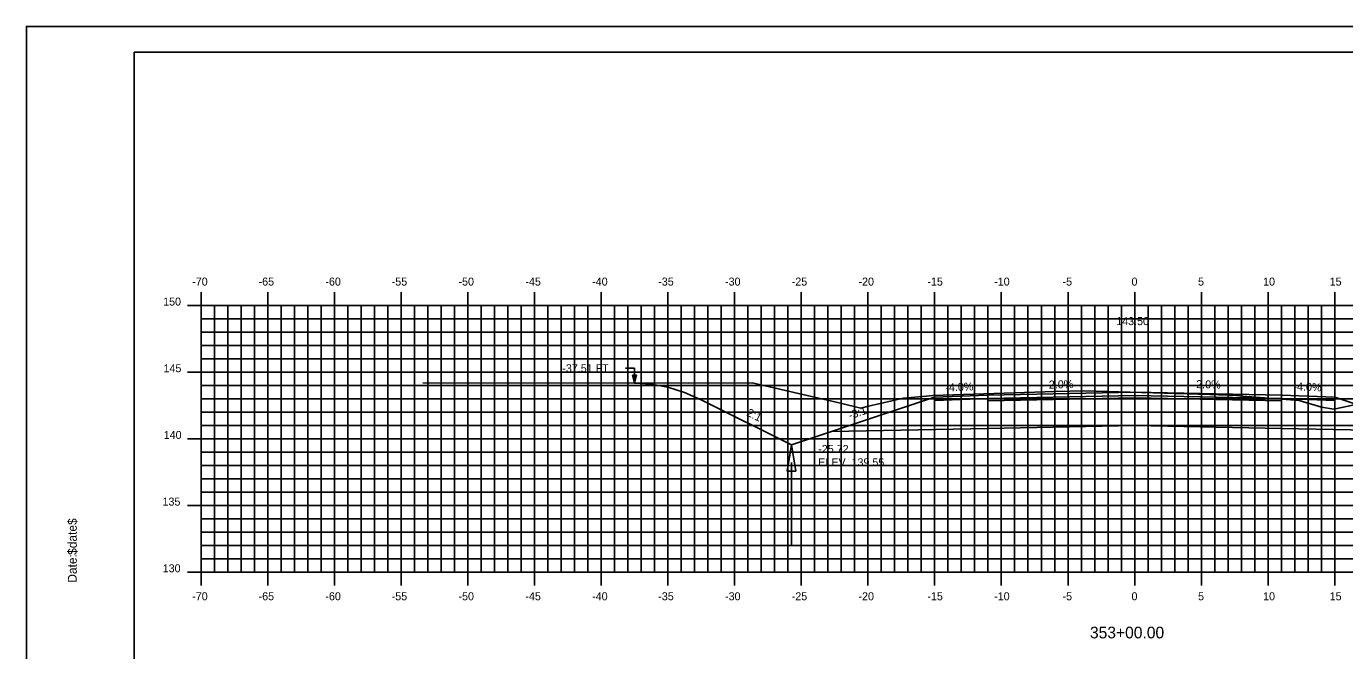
# Model space of a CAD drawing. Extents: x 1144972 to 1145142, y 608981 to 609091.
# Drawn here: x 1144972.3 to 1145071.1, y 609044.5 to 609091.3 of the extents above; entities that cross this region are included whole.
import ezdxf

# ---------------------------------------------------------------- set-up
doc = ezdxf.new("R2010")
doc.units = 0
for name, color, linetype in [('ANNOTATION', 7, 'Continuous'), ('BORDER', 7, 'Continuous'), ('D_Drainage_Ditch_Line', 7, 'Continuous'), ('D_Roadway_Centerline', 7, 'Continuous'), ('D_Roadway_Centerline_Text', 7, 'Continuous'), ('D_Roadway_Edge_Shoulder', 7, 'Continuous'), ('D_Roadway_Edge_TW', 7, 'Continuous'), ('D_Roadway_Pavement', 7, 'Continuous'), ('D_Roadway_SlopeLines', 7, 'Continuous'), ('D_Roadway_SubGrade', 7, 'Continuous'), ('D_Text_Standard', 7, 'Continuous'), ('H_V ANNOTATION', 7, 'Continuous'), ('MAJOR', 7, 'Continuous'), ('MINOR', 7, 'Continuous'), ('PLOT BOUNDARY', 7, 'Continuous'), ('S_Roadway_Centerline', 7, 'Continuous')]:
    doc.layers.add(name, color=color, linetype=linetype)

msp = doc.modelspace()

# ---------------------------------------------------------------- linework, layer by layer
msp.add_lwpolyline([(1145017.869, 609064.526), (1145019.119, 609064.447), (1145020.369, 609064.213), (1145021.619, 609063.822), (1145022.869, 609063.275), (1145029.651, 609059.884), (1145032.651, 609060.884), (1145040.374, 609063.458), (1145040.375, 609063.458), (1145044.375, 609063.618), (1145055.375, 609063.838), (1145066.375, 609063.618), (1145070.375, 609063.458), (1145078.099, 609060.884), (1145081.099, 609059.884), (1145086.647, 609062.658), (1145087.897, 609063.206), (1145089.147, 609063.599), (1145090.397, 609063.839), (1145091.647, 609063.924)])
at = {"layer": 'BORDER'}
msp.add_lwpolyline([(1144980.376, 608984.335), (1145140.376, 608984.335), (1145140.376, 609089.335), (1144980.376, 609089.335)], close=True, dxfattribs=at)
at = {"layer": 'D_Drainage_Ditch_Line'}
msp.add_line((1145029.651, 609058.571), (1145029.65, 609052.328), dxfattribs=at)
msp.add_lwpolyline([(1145029.979, 609057.915), (1145029.323, 609057.915), (1145029.651, 609059.884)], close=True, dxfattribs=at)
at = {"layer": 'D_Roadway_Edge_Shoulder'}
for points in [[(1145044.375, 609063.618), (1145040.375, 609063.458), (1145040.375, 609063.208), (1145044.375, 609063.368)], [(1145066.375, 609063.618), (1145070.375, 609063.458), (1145070.375, 609063.208), (1145066.375, 609063.368)]]:
    msp.add_lwpolyline(points, close=True, dxfattribs=at)
at = {"layer": 'D_Roadway_Edge_TW'}
msp.add_lwpolyline([(1145044.375, 609063.368), (1145044.375, 609063.618), (1145055.375, 609063.838), (1145066.375, 609063.618), (1145066.375, 609063.368), (1145055.375, 609063.588)], close=True, dxfattribs=at)
at = {"layer": 'D_Roadway_Pavement'}
msp.add_lwpolyline([(1145044.375, 609063.202), (1145044.375, 609063.368), (1145055.375, 609063.588), (1145066.375, 609063.368), (1145066.375, 609063.202), (1145055.375, 609063.422)], close=True, dxfattribs=at)
at = {"layer": 'D_Roadway_SlopeLines'}
for points in [[(1145029.651, 609059.884), (1145022.869, 609063.275), (1145021.619, 609063.822), (1145020.369, 609064.213), (1145019.119, 609064.447), (1145017.869, 609064.526)], [(1145032.651, 609060.884), (1145029.651, 609059.884)]]:
    msp.add_lwpolyline(points, dxfattribs=at)
at = {"layer": 'D_Roadway_SubGrade'}
for points in [[(1145044.375, 609063.202), (1145044.375, 609063.368), (1145040.375, 609063.208), (1145040.375, 609063.458), (1145040.374, 609063.458), (1145032.651, 609060.884), (1145044.375, 609061.118)], [(1145044.375, 609061.118), (1145044.375, 609063.202), (1145055.375, 609063.422), (1145066.375, 609063.202), (1145066.375, 609061.118), (1145055.375, 609061.338)], [(1145066.375, 609063.202), (1145066.375, 609063.368), (1145070.375, 609063.208), (1145070.375, 609063.458), (1145070.376, 609063.458), (1145078.099, 609060.884), (1145066.375, 609061.118)]]:
    msp.add_lwpolyline(points, close=True, dxfattribs=at)
at = {"layer": 'D_Text_Standard'}
msp.add_lwpolyline([(1145017.869, 609064.525), (1145017.871, 609065.634), (1145017.191, 609065.634)], dxfattribs=at)
msp.add_lwpolyline([(1145017.869, 609064.525), (1145017.725, 609065.107), (1145018.016, 609065.107)], close=True, dxfattribs=at)
at = {"layer": 'MAJOR'}
for p, q in [((1144985.375, 609071.337), (1144985.375, 609070.335)), ((1144990.375, 609071.337), (1144990.375, 609070.335)), ((1144995.375, 609071.337), (1144995.375, 609070.335)), ((1145000.375, 609071.337), (1145000.375, 609070.335)), ((1145005.375, 609071.337), (1145005.375, 609070.335)), ((1145010.375, 609071.337), (1145010.375, 609070.335)), ((1145015.375, 609071.337), (1145015.375, 609070.335)), ((1145020.375, 609071.337), (1145020.375, 609070.335)), ((1145025.375, 609071.337), (1145025.375, 609070.335)), ((1145030.375, 609071.337), (1145030.375, 609070.335)), ((1145035.375, 609071.337), (1145035.375, 609070.335)), ((1145040.375, 609071.337), (1145040.375, 609070.335)), ((1145045.375, 609071.337), (1145045.375, 609070.335)), ((1145050.375, 609071.337), (1145050.375, 609070.335)), ((1145055.375, 609071.337), (1145055.375, 609070.335)), ((1145060.375, 609071.337), (1145060.375, 609070.335)), ((1145065.375, 609071.337), (1145065.375, 609070.335)), ((1145070.375, 609071.337), (1145070.375, 609070.335)), ((1144984.373, 609070.335), (1144985.375, 609070.335)), ((1144985.375, 609070.335), (1145125.375, 609070.335)), ((1144985.375, 609050.335), (1144985.375, 609070.335)), ((1144985.375, 609050.335), (1144985.375, 609070.335)), ((1144985.375, 609070.335), (1145125.375, 609070.335)), ((1144990.375, 609050.335), (1144990.375, 609070.335)), ((1144995.375, 609050.335), (1144995.375, 609070.335)), ((1145000.375, 609050.335), (1145000.375, 609070.335)), ((1145005.375, 609050.335), (1145005.375, 609070.335)), ((1145010.375, 609050.335), (1145010.375, 609070.335)), ((1145015.375, 609050.335), (1145015.375, 609070.335)), ((1145020.375, 609050.335), (1145020.375, 609070.335)), ((1145025.375, 609050.335), (1145025.375, 609070.335)), ((1145030.375, 609050.335), (1145030.375, 609070.335)), ((1145035.375, 609050.335), (1145035.375, 609070.335)), ((1145040.375, 609050.335), (1145040.375, 609070.335)), ((1145045.375, 609050.335), (1145045.375, 609070.335)), ((1145050.375, 609050.335), (1145050.375, 609070.335)), ((1145055.375, 609050.335), (1145055.375, 609070.335)), ((1145060.375, 609050.335), (1145060.375, 609070.335)), ((1145065.375, 609050.335), (1145065.375, 609070.335)), ((1145070.375, 609050.335), (1145070.375, 609070.335)), ((1144984.373, 609065.335), (1144985.375, 609065.335)), ((1144985.375, 609065.335), (1145125.375, 609065.335)), ((1144984.373, 609060.335), (1144985.375, 609060.335)), ((1144985.375, 609060.335), (1145125.375, 609060.335)), ((1144984.373, 609055.335), (1144985.375, 609055.335)), ((1144985.375, 609055.335), (1145125.375, 609055.335)), ((1144984.373, 609050.335), (1144985.375, 609050.335)), ((1144985.375, 609050.335), (1145125.375, 609050.335)), ((1144985.375, 609050.335), (1145125.375, 609050.335)), ((1144985.375, 609049.333), (1144985.375, 609050.335)), ((1144990.375, 609049.333), (1144990.375, 609050.335)), ((1144995.375, 609049.333), (1144995.375, 609050.335)), ((1145000.375, 609049.333), (1145000.375, 609050.335)), ((1145005.375, 609049.333), (1145005.375, 609050.335)), ((1145010.375, 609049.333), (1145010.375, 609050.335)), ((1145015.375, 609049.333), (1145015.375, 609050.335)), ((1145020.375, 609049.333), (1145020.375, 609050.335)), ((1145025.375, 609049.333), (1145025.375, 609050.335)), ((1145030.375, 609049.333), (1145030.375, 609050.335)), ((1145035.375, 609049.333), (1145035.375, 609050.335)), ((1145040.375, 609049.333), (1145040.375, 609050.335)), ((1145045.375, 609049.333), (1145045.375, 609050.335)), ((1145050.375, 609049.333), (1145050.375, 609050.335)), ((1145055.375, 609049.333), (1145055.375, 609050.335)), ((1145060.375, 609049.333), (1145060.375, 609050.335)), ((1145065.375, 609049.333), (1145065.375, 609050.335)), ((1145070.375, 609049.333), (1145070.375, 609050.335))]:
    msp.add_line(p, q, dxfattribs=at)
at = {"layer": 'MINOR'}
for p, q in [((1144986.375, 609050.335), (1144986.375, 609070.335)), ((1144987.375, 609050.335), (1144987.375, 609070.335)), ((1144988.375, 609050.335), (1144988.375, 609070.335)), ((1144989.375, 609050.335), (1144989.375, 609070.335)), ((1144991.375, 609050.335), (1144991.375, 609070.335)), ((1144992.375, 609050.335), (1144992.375, 609070.335)), ((1144993.375, 609050.335), (1144993.375, 609070.335)), ((1144994.375, 609050.335), (1144994.375, 609070.335)), ((1144996.375, 609050.335), (1144996.375, 609070.335)), ((1144997.375, 609050.335), (1144997.375, 609070.335)), ((1144998.375, 609050.335), (1144998.375, 609070.335)), ((1144999.375, 609050.335), (1144999.375, 609070.335)), ((1145001.375, 609050.335), (1145001.375, 609070.335)), ((1145002.375, 609050.335), (1145002.375, 609070.335)), ((1145003.375, 609050.335), (1145003.375, 609070.335)), ((1145004.375, 609050.335), (1145004.375, 609070.335)), ((1145006.375, 609050.335), (1145006.375, 609070.335)), ((1145007.375, 609050.335), (1145007.375, 609070.335)), ((1145008.375, 609050.335), (1145008.375, 609070.335)), ((1145009.375, 609050.335), (1145009.375, 609070.335)), ((1145011.375, 609050.335), (1145011.375, 609070.335)), ((1145012.375, 609050.335), (1145012.375, 609070.335)), ((1145013.375, 609050.335), (1145013.375, 609070.335)), ((1145014.375, 609050.335), (1145014.375, 609070.335)), ((1145016.375, 609050.335), (1145016.375, 609070.335)), ((1145017.375, 609050.335), (1145017.375, 609070.335)), ((1145018.375, 609050.335), (1145018.375, 609070.335)), ((1145019.375, 609050.335), (1145019.375, 609070.335)), ((1145021.375, 609050.335), (1145021.375, 609070.335)), ((1145022.375, 609050.335), (1145022.375, 609070.335)), ((1145023.375, 609050.335), (1145023.375, 609070.335)), ((1145024.375, 609050.335), (1145024.375, 609070.335)), ((1145026.375, 609050.335), (1145026.375, 609070.335)), ((1145027.375, 609050.335), (1145027.375, 609070.335)), ((1145028.375, 609050.335), (1145028.375, 609070.335)), ((1145029.375, 609050.335), (1145029.375, 609070.335)), ((1145031.375, 609050.335), (1145031.375, 609070.335)), ((1145032.375, 609050.335), (1145032.375, 609070.335)), ((1145033.375, 609050.335), (1145033.375, 609070.335)), ((1145034.375, 609050.335), (1145034.375, 609070.335)), ((1145036.375, 609050.335), (1145036.375, 609070.335)), ((1145037.375, 609050.335), (1145037.375, 609070.335)), ((1145038.375, 609050.335), (1145038.375, 609070.335)), ((1145039.375, 609050.335), (1145039.375, 609070.335)), ((1145041.375, 609050.335), (1145041.375, 609070.335)), ((1145042.375, 609050.335), (1145042.375, 609070.335)), ((1145043.375, 609050.335), (1145043.375, 609070.335)), ((1145044.375, 609050.335), (1145044.375, 609070.335)), ((1145046.375, 609050.335), (1145046.375, 609070.335)), ((1145047.375, 609050.335), (1145047.375, 609070.335)), ((1145048.375, 609050.335), (1145048.375, 609070.335)), ((1145049.375, 609050.335), (1145049.375, 609070.335)), ((1145051.375, 609050.335), (1145051.375, 609070.335)), ((1145052.375, 609050.335), (1145052.375, 609070.335)), ((1145053.375, 609050.335), (1145053.375, 609070.335)), ((1145054.375, 609050.335), (1145054.375, 609070.335)), ((1145056.375, 609050.335), (1145056.375, 609070.335)), ((1145057.375, 609050.335), (1145057.375, 609070.335)), ((1145058.375, 609050.335), (1145058.375, 609070.335)), ((1145059.375, 609050.335), (1145059.375, 609070.335)), ((1145061.375, 609050.335), (1145061.375, 609070.335)), ((1145062.375, 609050.335), (1145062.375, 609070.335)), ((1145063.375, 609050.335), (1145063.375, 609070.335)), ((1145064.375, 609050.335), (1145064.375, 609070.335)), ((1145066.375, 609050.335), (1145066.375, 609070.335)), ((1145067.375, 609050.335), (1145067.375, 609070.335)), ((1145068.375, 609050.335), (1145068.375, 609070.335)), ((1145069.375, 609050.335), (1145069.375, 609070.335)), ((1144985.375, 609069.335), (1145125.375, 609069.335)), ((1144985.375, 609069.335), (1144986.377, 609069.335)), ((1144985.375, 609068.335), (1145125.375, 609068.335)), ((1144985.375, 609068.335), (1144986.377, 609068.335)), ((1144985.375, 609067.335), (1145125.375, 609067.335)), ((1144985.375, 609067.335), (1144986.377, 609067.335)), ((1144985.375, 609066.335), (1145125.375, 609066.335)), ((1144985.375, 609066.335), (1144986.377, 609066.335)), ((1144985.375, 609064.335), (1145125.375, 609064.335)), ((1144985.375, 609064.335), (1144986.377, 609064.335)), ((1144985.375, 609063.335), (1145125.375, 609063.335)), ((1144985.375, 609063.335), (1144986.377, 609063.335)), ((1144985.375, 609062.335), (1145125.375, 609062.335)), ((1144985.375, 609062.335), (1144986.377, 609062.335)), ((1144985.375, 609061.335), (1145125.375, 609061.335)), ((1144985.375, 609061.335), (1144986.377, 609061.335)), ((1144985.375, 609059.335), (1145125.375, 609059.335)), ((1144985.375, 609059.335), (1144986.377, 609059.335)), ((1144985.375, 609058.335), (1145125.375, 609058.335)), ((1144985.375, 609058.335), (1144986.377, 609058.335)), ((1144985.375, 609057.335), (1145125.375, 609057.335)), ((1144985.375, 609057.335), (1144986.377, 609057.335)), ((1144985.375, 609056.335), (1145125.375, 609056.335)), ((1144985.375, 609056.335), (1144986.377, 609056.335)), ((1144985.375, 609054.335), (1145125.375, 609054.335)), ((1144985.375, 609054.335), (1144986.377, 609054.335)), ((1144985.375, 609053.335), (1145125.375, 609053.335)), ((1144985.375, 609053.335), (1144986.377, 609053.335)), ((1144985.375, 609052.335), (1145125.375, 609052.335)), ((1144985.375, 609052.335), (1144986.377, 609052.335)), ((1144985.375, 609051.335), (1145125.375, 609051.335)), ((1144985.375, 609051.335), (1144986.377, 609051.335))]:
    msp.add_line(p, q, dxfattribs=at)
at = {"layer": 'PLOT BOUNDARY'}
msp.add_lwpolyline([(1144972.282, 608981.276), (1145142.282, 608981.276), (1145142.282, 609091.276), (1144972.282, 609091.276)], close=True, dxfattribs=at)
at = {"layer": 'S_Roadway_Centerline'}
msp.add_lwpolyline([(1145001.997, 609064.533), (1145021.959, 609064.524), (1145026.689, 609064.539), (1145033.328, 609063.015), (1145034.845, 609062.632), (1145035.408, 609062.786), (1145038.043, 609063.382), (1145039.736, 609063.551), (1145040.242, 609063.584), (1145049.415, 609063.888), (1145051.636, 609063.943), (1145061.011, 609063.662), (1145062.985, 609063.582), (1145063.485, 609063.534), (1145067.713, 609063.215), (1145069.391, 609062.729), (1145070.304, 609062.563), (1145071.368, 609062.797), (1145075.896, 609063.823), (1145094.4, 609063.941), (1145101.628, 609064.155)], dxfattribs=at)

# ---------------------------------------------------------------- texts
at = {"layer": 'ANNOTATION'}
for s, rotation, p in [('-4.0%', 2.29061, (1145041.191, 609063.892)), ('-2.0%', 1.14576, (1145048.678, 609064.105)), ('-2.0%', 358.85424, (1145059.718, 609064.152)), ('-4.0%', 357.70939, (1145067.271, 609063.983)), ('2:1', 333.43495, (1145026.227, 609062.114)), ('-3:1', 18.43482, (1145034.03, 609061.797))]:
    msp.add_text(s, height=0.6, rotation=rotation, dxfattribs=at).set_placement(p)
at = {"layer": 'BORDER'}
for s, p in [('$date$', (1144976.061, 609051.64)), ('Date:', (1144976.061, 609049.552))]:
    msp.add_text(s, height=0.6696, rotation=90, dxfattribs=at).set_placement(p)
at = {"layer": 'D_Roadway_Centerline'}
for s, p in [('C', (1145055.37, 609063.838)), ('L', (1145055.375, 609063.831))]:
    msp.add_text(s, height=0.0146, dxfattribs=at).set_placement(p)
at = {"layer": 'D_Roadway_Centerline_Text'}
msp.add_text('143.50', height=0.6, dxfattribs=at).set_placement((1145053.99, 609068.87))
at = {"layer": 'D_Text_Standard'}
for s, p in [('-37.51 FT', (1145012.465, 609065.334)), ('-25.72', (1145031.651, 609059.284)), ('ELEV. 139.55', (1145031.651, 609058.282))]:
    msp.add_text(s, height=0.6, dxfattribs=at).set_placement(p)
at = {"layer": 'H_V ANNOTATION'}
for s, height, p in [('-70', 0.6, (1144984.717, 609071.835)), ('-65', 0.6, (1144989.693, 609071.835)), ('-60', 0.6, (1144994.701, 609071.835)), ('-55', 0.6, (1144999.672, 609071.835)), ('-50', 0.6, (1145004.68, 609071.835)), ('-45', 0.6, (1145009.693, 609071.835)), ('-40', 0.6, (1145014.701, 609071.835)), ('-35', 0.6, (1145019.656, 609071.835)), ('-30', 0.6, (1145024.664, 609071.835)), ('-25', 0.6, (1145029.661, 609071.835)), ('-20', 0.6, (1145034.669, 609071.835)), ('-15', 0.6, (1145039.832, 609071.835)), ('-10', 0.6, (1145044.84, 609071.835)), ('-5', 0.6, (1145049.966, 609071.835)), ('0', 0.6, (1145055.135, 609071.835)), ('5', 0.6, (1145060.126, 609071.835)), ('10', 0.6, (1145065.001, 609071.835)), ('15', 0.6, (1145069.993, 609071.835)), ('150', 0.6, (1144982.537, 609070.335)), ('145', 0.6, (1144982.564, 609065.335)), ('140', 0.6, (1144982.58, 609060.335)), ('135', 0.6, (1144982.489, 609055.335)), ('130', 0.6, (1144982.505, 609050.335)), ('-70', 0.6, (1144984.717, 609048.235)), ('-65', 0.6, (1144989.693, 609048.235)), ('-60', 0.6, (1144994.701, 609048.235)), ('-55', 0.6, (1144999.672, 609048.235)), ('-50', 0.6, (1145004.68, 609048.235)), ('-45', 0.6, (1145009.693, 609048.235)), ('-40', 0.6, (1145014.701, 609048.235)), ('-35', 0.6, (1145019.656, 609048.235)), ('-30', 0.6, (1145024.664, 609048.235)), ('-25', 0.6, (1145029.661, 609048.235)), ('-20', 0.6, (1145034.669, 609048.235)), ('-15', 0.6, (1145039.832, 609048.235)), ('-10', 0.6, (1145044.84, 609048.235)), ('-5', 0.6, (1145049.966, 609048.235)), ('0', 0.6, (1145055.135, 609048.235)), ('5', 0.6, (1145060.126, 609048.235)), ('10', 0.6, (1145065.001, 609048.235)), ('15', 0.6, (1145069.993, 609048.235)), ('353+00.00', 0.875, (1145052.02, 609045.378))]:
    msp.add_text(s, height=height, dxfattribs=at).set_placement(p)
at = {"layer": 'MAJOR'}
msp.add_text('-', height=0.006, dxfattribs=at).set_placement((1144985.371, 609050.335))
at = {"layer": 'S_Roadway_Centerline'}
for s, p in [('L', (1145051.628, 609063.936)), ('C', (1145051.631, 609063.943))]:
    msp.add_text(s, height=0.0146, dxfattribs=at).set_placement(p)

doc.saveas('drawing.dxf')
